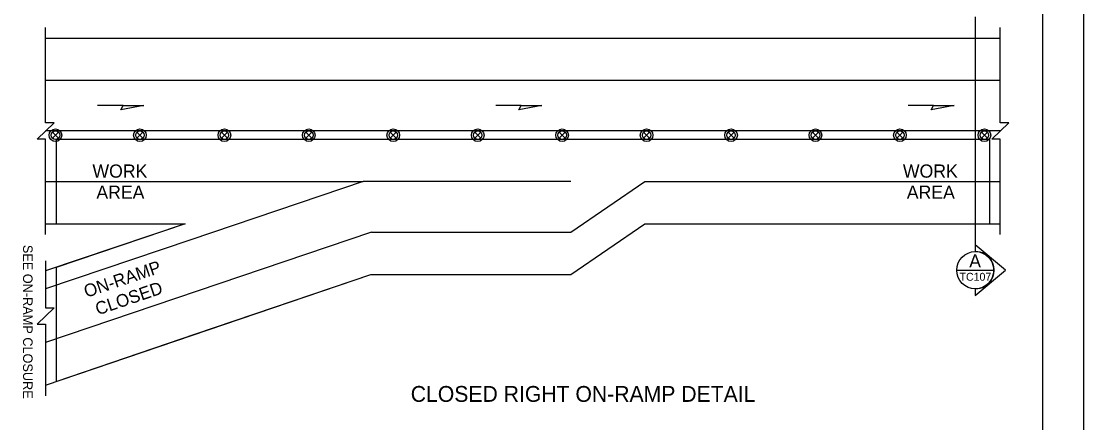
# Model space of a CAD drawing. Extents: x 99999 to 100116, y 99995 to 100013.
# Drawn here: x 100048.01 to 100056.06, y 100001.64 to 100004.69 of the extents above; entities that cross this region are included whole.
import ezdxf

# ---------------------------------------------------------------- set-up
doc = ezdxf.new("R2010")
doc.units = 0
for name, color, linetype in [('RD_MK_LineEdgeYellow', 7, 'Continuous'), ('RD_MK_LineLane', 7, 'Continuous'), ('SH_DE_DetailHeading2Text', 7, 'Continuous'), ('SH_GI_PlotLimits', 7, 'Continuous'), ('SH_GI_SheetBorder', 7, 'Continuous'), ('SH_TI_WZSectionCut', 7, 'Continuous'), ('TR_WZ_TrafficSafetyDrum', 7, 'Continuous'), ('TR_WZ_WorkAreaLabel', 7, 'Continuous'), ('TR_WZ_WorkZoneDetails', 7, 'Continuous')]:
    doc.layers.add(name, color=color, linetype=linetype)

msp = doc.modelspace()

# ---------------------------------------------------------------- linework, layer by layer
at = {"layer": 'RD_MK_LineEdgeYellow'}
for p, q in [((100048.195, 100004.238), (100055.43, 100004.238)), ((100048.195, 100003.47), (100049.2533, 100003.47)), ((100052.1758, 100003.086), (100052.7368, 100003.47)), ((100052.7368, 100003.47), (100055.43, 100003.47)), ((100050.6655, 100003.086), (100048.195, 100002.2517)), ((100049.2943, 100003.0282), (100048.195, 100002.657)), ((100050.6655, 100003.086), (100052.1758, 100003.086))]:
    msp.add_line(p, q, dxfattribs=at)
at = {"layer": 'RD_MK_LineLane'}
for points in [[(100055.43, 100003.854), (100048.195, 100003.854)], [(100052.1758, 100003.47), (100050.6024, 100003.47)]]:
    msp.add_lwpolyline(points, dxfattribs=at)
at = {"layer": 'SH_GI_PlotLimits'}
msp.add_lwpolyline([(100039.0625, 99999.6875), (100056.0625, 99999.6875), (100056.0625, 100010.6875), (100039.0625, 100010.6875)], close=True, dxfattribs=at)
at = {"layer": 'SH_GI_SheetBorder'}
msp.add_line((100055.75, 100010.375), (100055.75, 100000), dxfattribs=at)
at = {"layer": 'SH_TI_WZSectionCut'}
for p, q in [((100055.2407, 100004.718), (100055.2407, 100002.99)), ((100055.2407, 100002.99), (100055.2407, 100002.94)), ((100055.4689, 100002.7988), (100055.2407, 100002.99)), ((100055.2407, 100002.6077), (100055.4689, 100002.7988)), ((100055.2407, 100002.6576), (100055.2407, 100002.6077))]:
    msp.add_line(p, q, dxfattribs=at)
msp.add_lwpolyline([(100055.0995, 100002.7988), (100055.3819, 100002.7988)], dxfattribs=at)
msp.add_circle((100055.2407, 100002.7988), 0.1412, dxfattribs=at)
msp.add_arc((100055.2407, 100002.7988), 0.1412, 269.99779, 90.00221, dxfattribs=at)
at = {"layer": 'TR_WZ_TrafficSafetyDrum'}
for p, q in [((100048.2468, 100003.8446), (100048.292, 100003.7993)), ((100048.292, 100003.8446), (100048.2468, 100003.7993)), ((100048.8868, 100003.8446), (100048.932, 100003.7993)), ((100048.932, 100003.8446), (100048.8868, 100003.7993)), ((100049.5268, 100003.8446), (100049.572, 100003.7993)), ((100049.572, 100003.8446), (100049.5268, 100003.7993)), ((100050.1668, 100003.8446), (100050.212, 100003.7993)), ((100050.212, 100003.8446), (100050.1668, 100003.7993)), ((100050.8068, 100003.8446), (100050.852, 100003.7993)), ((100050.852, 100003.8446), (100050.8068, 100003.7993)), ((100051.4468, 100003.8446), (100051.492, 100003.7993)), ((100051.492, 100003.8446), (100051.4468, 100003.7993)), ((100052.0868, 100003.8446), (100052.132, 100003.7993)), ((100052.132, 100003.8446), (100052.0868, 100003.7993)), ((100052.7268, 100003.8446), (100052.772, 100003.7993)), ((100052.772, 100003.8446), (100052.7268, 100003.7993)), ((100053.3668, 100003.8446), (100053.412, 100003.7993)), ((100053.412, 100003.8446), (100053.3668, 100003.7993)), ((100054.0068, 100003.8446), (100054.052, 100003.7993)), ((100054.052, 100003.8446), (100054.0068, 100003.7993)), ((100054.6468, 100003.8446), (100054.692, 100003.7993)), ((100054.692, 100003.8446), (100054.6468, 100003.7993)), ((100055.2868, 100003.8446), (100055.332, 100003.7993)), ((100055.332, 100003.8446), (100055.2868, 100003.7993))]:
    msp.add_line(p, q, dxfattribs=at)
for centre, radius in [((100048.2694, 100003.822), 0.048), ((100048.2694, 100003.822), 0.048), ((100048.2694, 100003.822), 0.032), ((100048.9094, 100003.822), 0.048), ((100048.9094, 100003.822), 0.048), ((100048.9094, 100003.822), 0.032), ((100049.5494, 100003.822), 0.048), ((100049.5494, 100003.822), 0.048), ((100049.5494, 100003.822), 0.032), ((100050.1894, 100003.822), 0.048), ((100050.1894, 100003.822), 0.048), ((100050.1894, 100003.822), 0.032), ((100050.8294, 100003.822), 0.048), ((100050.8294, 100003.822), 0.048), ((100050.8294, 100003.822), 0.032), ((100051.4694, 100003.822), 0.048), ((100051.4694, 100003.822), 0.048), ((100051.4694, 100003.822), 0.032), ((100052.1094, 100003.822), 0.048), ((100052.1094, 100003.822), 0.048), ((100052.1094, 100003.822), 0.032), ((100052.7494, 100003.822), 0.048), ((100052.7494, 100003.822), 0.048), ((100052.7494, 100003.822), 0.032), ((100053.3894, 100003.822), 0.048), ((100053.3894, 100003.822), 0.048), ((100053.3894, 100003.822), 0.032), ((100054.0294, 100003.822), 0.048), ((100054.0294, 100003.822), 0.048), ((100054.0294, 100003.822), 0.032), ((100054.6694, 100003.822), 0.048), ((100054.6694, 100003.822), 0.048), ((100054.6694, 100003.822), 0.032), ((100055.3094, 100003.822), 0.048), ((100055.3094, 100003.822), 0.048), ((100055.3094, 100003.822), 0.032)]:
    msp.add_circle(centre, radius, dxfattribs=at)
at = {"layer": 'TR_WZ_WorkZoneDetails'}
for p, q in [((100048.195, 100004.558), (100055.43, 100004.558)), ((100048.782, 100004.046), (100048.5891, 100004.046)), ((100051.7994, 100004.046), (100051.6065, 100004.046)), ((100054.9242, 100004.046), (100054.7313, 100004.046)), ((100049.2533, 100003.47), (100050.6024, 100003.47)), ((100050.6024, 100003.47), (100049.2943, 100003.0282)), ((100048.195, 100003.15), (100049.2533, 100003.15)), ((100049.2533, 100003.15), (100048.195, 100002.7929)), ((100052.1758, 100002.766), (100052.7368, 100003.15)), ((100052.7368, 100003.15), (100055.43, 100003.15)), ((100048.195, 100001.928), (100050.6601, 100002.766)), ((100050.6601, 100002.766), (100052.1758, 100002.766))]:
    msp.add_line(p, q, dxfattribs=at)
for points in [[(100048.195, 100003.07), (100048.195, 100003.792), (100048.131, 100003.792), (100048.259, 100003.9159), (100048.195, 100003.9159), (100048.195, 100004.638)], [(100055.43, 100003.07), (100055.43, 100003.792), (100055.366, 100003.792), (100055.494, 100003.9159), (100055.43, 100003.9159), (100055.43, 100004.638)], [(100048.195, 100002.8701), (100048.195, 100002.5136), (100048.259, 100002.5136), (100048.131, 100002.3897), (100048.195, 100002.3897), (100048.195, 100001.8453)]]:
    msp.add_lwpolyline(points, dxfattribs=at)
for points in [[(100048.9392, 100004.046), (100048.7641, 100004.0151), (100048.782, 100004.046)], [(100051.9566, 100004.046), (100051.7815, 100004.0151), (100051.7994, 100004.046)], [(100055.0815, 100004.046), (100054.9064, 100004.0151), (100054.9242, 100004.046)], [(100048.275, 100003.79), (100048.275, 100003.15), (100049.2533, 100003.15), (100048.275, 100002.8199), (100048.275, 100002.8199), (100048.275, 100002.8199), (100048.275, 100001.9552), (100048.275, 100001.9552), (100048.275, 100001.9552), (100049.3341, 100002.3152), (100050.6601, 100002.766), (100052.1758, 100002.766), (100052.7368, 100003.15), (100055.35, 100003.15), (100055.35, 100003.79)]]:
    msp.add_lwpolyline(points, close=True, dxfattribs=at)

# ---------------------------------------------------------------- texts
at = {"layer": 'SH_DE_DetailHeading2Text'}
msp.add_text('CLOSED RIGHT ON-RAMP DETAIL', height=0.12, rotation=360, dxfattribs=at).set_placement((100050.9618, 100001.8009))
at = {"layer": 'SH_TI_WZSectionCut'}
for s, height, rotation, p in [('A', 0.1, 0.00995, (100055.1945, 100002.8195)), ('TC107', 0.06, 360, (100055.1209, 100002.7188))]:
    msp.add_text(s, height=height, rotation=rotation, dxfattribs=at).set_placement(p)
at = {"layer": 'TR_WZ_WorkAreaLabel'}
for s, p in [('WORK', (100048.5496, 100003.5)), ('WORK', (100054.6919, 100003.5)), ('AREA', (100048.5793, 100003.34)), ('AREA', (100054.7215, 100003.34))]:
    msp.add_text(s, height=0.1, dxfattribs=at).set_placement(p)
at = {"layer": 'TR_WZ_WorkZoneDetails'}
for s, height, rotation, p in [('SEE ON-RAMP CLOSURE', 0.072, 270, (100048.0238, 100002.9908)), ('ON-RAMP', 0.096, 18.65903, (100048.5039, 100002.589)), ('ON-RAMP', 0.096, 18.65903, (100048.5039, 100002.589)), ('CLOSED', 0.096, 18.65903, (100048.5907, 100002.4562)), ('CLOSED', 0.096, 18.65903, (100048.5907, 100002.4562))]:
    msp.add_text(s, height=height, rotation=rotation, dxfattribs=at).set_placement(p)

doc.saveas('drawing.dxf')
